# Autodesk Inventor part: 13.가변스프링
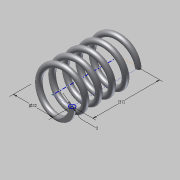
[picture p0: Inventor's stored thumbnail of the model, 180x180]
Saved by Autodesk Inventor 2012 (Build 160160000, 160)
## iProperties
Created: 2014-12
Part Number: 13.가변스프링
Material: Default
Document SubType Name: Modeling
Designer: HOME
Density: 1 g/cm^3
Mass: 2.39545 g
Surface Area: 32.5161 cm^2
Volume: 2.39545 cm^3
Author: HOME
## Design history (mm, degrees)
sketch "스케치1"
  geometry: L1 (0, 0)-(11, 0); L2 (11, 0)-(11, 25.358); L3 (11, 25.358)-(0, 25.358); L4 (0, 25.358)-(0, 0); C1 r 1.5 at (11, 0); 1 further point
  constraints: 8 end point, 2 coincident, 2 parallel, 1 centre point, 1 horizontal, 1 perpendicular
  dimensions: "d0" = 22 diameter of L2 L4; "d1" = 25.35829 distance of L1.end L2.end (derived); "d2" = 3 diameter of C1
feature "코일1" pitch "d3" = 10; turns "d5" = 5; dims "d4" = 25.35829 (= d1), "d6" = 0, angle "d7" = 90 deg, angle "d8" = 90 deg, "d9" = 0, "d10" = 0
sketch "스케치2"
  geometry: L1 (-12.5, 0)-(-9.5, 0) reference; 1 further point
  constraints: 1 horizontal alignment
extrude "돌출1" cut sketch "스케치2" stored distance "d11" = 10; taper "d12" = 0 deg
node "작업 평면1"
sketch "스케치3"
  geometry: L1 (-9.5, 0)-(-12.5, 0) reference; 1 further point
  constraints: 1 horizontal alignment
extrude "돌출2" cut sketch "스케치3" stored distance "d13" = 10; taper "d14" = 0 deg
node "솔리드1"
node "절단 모서리 투영1"
node "절단 모서리 투영2"
